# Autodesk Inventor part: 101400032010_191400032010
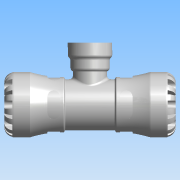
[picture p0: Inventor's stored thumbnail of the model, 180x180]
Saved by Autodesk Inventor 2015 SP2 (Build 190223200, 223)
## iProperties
Created: 2016-12
Part Number: 101400032010_191400032010
Material: PVC-Piping
Description: PLASSON TEE WITH THREADED FEMALE OFFTAKE 32X1" SERIES 1
Document SubType Name: Modeling
Designer: KIM
Mass: 664.223 g
Surface Area: 733.008 cm^2
Volume: 474.445 cm^3
Density: 1.4 g/cm^3
Appearance: Smooth - White
Author: KIM
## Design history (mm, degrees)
derived "1014.ipt"
feature "Solid1::1014.ipt"
tag "TaggingFeature1"
body "Solid1"
other parameters: "d1" = 22.68, "d2" = 32, "d4" = 58, "d8" = 49.3, "d13" = 7.2, "d14" = 7.2, "d15" = 0, "d17" = 360 deg, "d19" = 8 deg, "d20" = 0.64, "d21" = 0.64, "d22" = 8 deg, "d24" = 0, "d26" = 360 deg, "d33" = 5.8, "d43" = 45.24, "d51" = 0.58, "d54" = 11.2, "d55" = 7.04, "d57" = 14.112, "d58" = 0, "d74" = 0, "d77" = 2.66667, "d78" = 54, "d79" = 45.24, "d80" = 152, "d82" = 0.64, "d115" = 360 deg, "d139" = 7.2, "d140" = 0, "d142" = 360 deg, "d207" = 90 deg, "d228" = 9.52, "d247" = 1.16, "d248" = 3.24, "d266" = 0, "d268" = 30.291, "d270" = 4.54365, "d271" = 7, "d274" = 2.27183, "d275" = 55, "d276" = 3.0291, "d277" = 3.0291, "d278" = 3.0291, "d279" = 3.0291, "d281" = 0, "d282" = 21, "d_" = 32, "E_" = 58, "l_" = 54, "A_" = 55, "H_" = 152, "Rp_" = 30.291, "l_2" = 21, "d9" = 9, "d11" = 58
